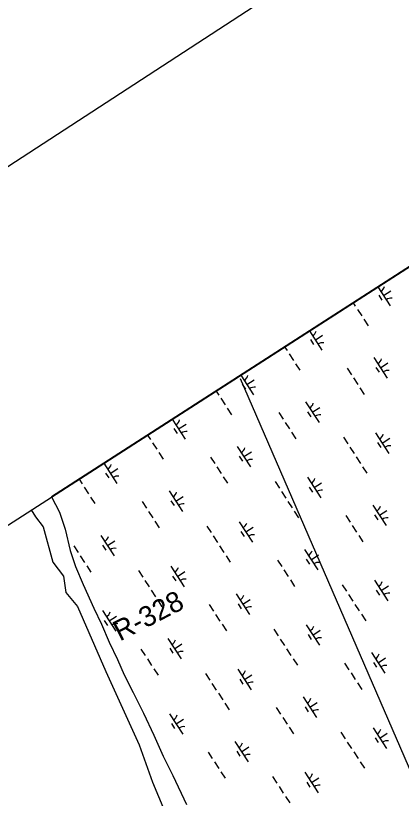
# Model space of a CAD drawing. Extents: x 3953924 to 3974542, y 193747 to 216192.
# Drawn here: x 3960506 to 3961293, y 210540 to 212138 of the extents above; entities that cross this region are included whole.
import ezdxf

# ---------------------------------------------------------------- set-up
doc = ezdxf.new("R2010")
doc.units = 0
for name, color, linetype in [('V-ANNO-SYMB', 7, 'Continuous'), ('V-GRID-FRAM', 7, 'Continuous'), ('V-RIVR-EDGE', 7, 'Continuous'), ('V-RIVR-RANG-IDEN', 7, 'Continuous'), ('V-UTIL-LINE', 7, 'Continuous'), ('V-WETL-SWMP', 7, 'Continuous')]:
    doc.layers.add(name, color=color, linetype=linetype)

msp = doc.modelspace()

# ---------------------------------------------------------------- linework, layer by layer
at = {"layer": 'V-ANNO-SYMB'}
msp.add_lwpolyline([(3955180.9, 208373.9), (3964205.1, 194510.7), (3973808.1, 200761.7), (3964783.9, 214624.9), (3955180.9, 208373.9)], dxfattribs=at)
at = {"layer": 'V-GRID-FRAM'}
msp.add_lwpolyline([(3964669.3, 213787.9), (3972946, 201072.9), (3966057, 196668.5), (3957950.8, 209463.9), (3964669.3, 213787.9)], dxfattribs=at)
at = {"layer": 'V-RIVR-EDGE'}
msp.add_lwpolyline([(3960538.1, 211129.1), (3960546.7, 211115.1), (3960562.1, 211094.9), (3960582.3, 211022.5), (3960603.7, 210994), (3960608.4, 210960.7), (3960632.2, 210932.2), (3960690.3, 210799.3), (3960758, 210649.7), (3960785.3, 210573.7), (3960818.5, 210494.2)], dxfattribs=at)
at = {"layer": 'V-UTIL-LINE'}
msp.add_lwpolyline([(3960964.1, 211397.1), (3962099.7, 208779.5)], dxfattribs=at)
at = {"layer": 'V-WETL-SWMP'}
for p, q in [((3962105.5, 212137.9), (3960579.5, 211155.8)), ((3961245.4, 211584.4), (3961270.6, 211545.7)), ((3961247.3, 211567.4), (3961253.8, 211557.4)), ((3961257, 211566.6), (3961272.1, 211576.4)), ((3961195, 211551.9), (3961199.4, 211545.1)), ((3961203.7, 211538.4), (3961212.5, 211525)), ((3961216.8, 211518.3), (3961225.5, 211504.9)), ((3961105.6, 211494.3), (3961131.2, 211454.9)), ((3961117.6, 211475.9), (3961132.7, 211485.7)), ((3961107.9, 211476.7), (3961114.4, 211466.6)), ((3961055.1, 211461.8), (3961060, 211454.4)), ((3961064.3, 211447.7), (3961073.1, 211434.2)), ((3961237.4, 211440.2), (3961264.7, 211398.3)), ((3961077.4, 211427.5), (3961086.1, 211414.1)), ((3961251, 211419.2), (3961266.1, 211429.1)), ((3961182.6, 211418.5), (3961191.4, 211405.1)), ((3961241.3, 211420.1), (3961247.8, 211410)), ((3960965.7, 211404.3), (3960991.8, 211364.2)), ((3960978.2, 211385.1), (3960993.3, 211394.9)), ((3961195.7, 211398.4), (3961204.4, 211385)), ((3960968.5, 211385.9), (3960975, 211375.9)), ((3961208.8, 211378.3), (3961217.5, 211364.9)), ((3960915.2, 211371.8), (3960920.6, 211363.6)), ((3960924.9, 211356.9), (3960933.6, 211343.5)), ((3961098, 211349.5), (3961125.3, 211307.5)), ((3960938, 211336.8), (3960946.7, 211323.4)), ((3961043.2, 211327.8), (3961051.9, 211314.4)), ((3961101.9, 211329.3), (3961108.4, 211319.3)), ((3961111.6, 211328.5), (3961126.7, 211338.3)), ((3960825.8, 211314.3), (3960852.4, 211273.4)), ((3960829, 211295.2), (3960835.6, 211285.1)), ((3960838.8, 211294.4), (3960853.9, 211304.2)), ((3961056.3, 211307.7), (3961065, 211294.3)), ((3960775.3, 211281.8), (3960781.2, 211272.9)), ((3961069.4, 211287.5), (3961078.1, 211274.1)), ((3961240.9, 211286.5), (3961268.1, 211244.6)), ((3960785.5, 211266.2), (3960794.2, 211252.8)), ((3961175, 211277.6), (3961183.8, 211264.2)), ((3961244.8, 211266.4), (3961251.3, 211256.3)), ((3961254.5, 211265.5), (3961269.6, 211275.4)), ((3960798.6, 211246.1), (3960807.3, 211232.6)), ((3960958.6, 211258.7), (3960985.8, 211216.8)), ((3960972.2, 211237.8), (3960987.3, 211247.6)), ((3961188.1, 211257.4), (3961196.9, 211244)), ((3960903.8, 211237), (3960912.5, 211223.6)), ((3960962.5, 211238.6), (3960969, 211228.5)), ((3961201.2, 211237.3), (3961210, 211223.9)), ((3960685.9, 211224.3), (3960713, 211182.7)), ((3960916.9, 211216.9), (3960925.6, 211203.5)), ((3961214.3, 211217.2), (3961223.1, 211203.8)), ((3960689.6, 211204.4), (3960696.2, 211194.4)), ((3960699.4, 211203.6), (3960714.5, 211213.4)), ((3960635.5, 211191.8), (3960641.7, 211182.1)), ((3960930, 211196.8), (3960938.7, 211183.4)), ((3961035.6, 211186.8), (3961044.4, 211173.4)), ((3961101.5, 211195.7), (3961128.7, 211153.8)), ((3961115.1, 211174.8), (3961130.2, 211184.6)), ((3960646.1, 211175.4), (3960654.8, 211162)), ((3960819.2, 211168), (3960846.4, 211126.1)), ((3961048.7, 211166.7), (3961057.5, 211153.3)), ((3961105.4, 211175.6), (3961111.9, 211165.6)), ((3960579.5, 211155.8), (3960595.7, 211124.3)), ((3960659.2, 211155.3), (3960667.9, 211141.9)), ((3960832.8, 211147), (3960847.9, 211156.8)), ((3960764.4, 211146.3), (3960773.1, 211132.9)), ((3960823.1, 211147.8), (3960829.6, 211137.8)), ((3961061.8, 211146.6), (3961070.6, 211133.2)), ((3961234.9, 211139.1), (3961262.2, 211097.2)), ((3960595.7, 211124.3), (3960607.4, 211089.6)), ((3960777.5, 211126.2), (3960786.2, 211112.8)), ((3961074.9, 211126.5), (3961083.6, 211113.1)), ((3961238.8, 211119), (3961245.3, 211108.9)), ((3961248.5, 211118.2), (3961263.6, 211128)), ((3960790.6, 211106.1), (3960799.3, 211092.6)), ((3960962.1, 211105), (3960989.3, 211063.1)), ((3961180.1, 211117.5), (3961188.9, 211104)), ((3960607.4, 211089.6), (3960617.2, 211046.5)), ((3960896.2, 211096.1), (3960905, 211082.7)), ((3960975.7, 211084.1), (3960990.8, 211093.9)), ((3961193.2, 211097.3), (3961201.9, 211083.9)), ((3960679.8, 211077.2), (3960707, 211035.3)), ((3960909.3, 211076), (3960918.1, 211062.5)), ((3960966, 211084.9), (3960972.5, 211074.8)), ((3961206.3, 211077.2), (3961215, 211063.8)), ((3960625, 211055.5), (3960633.7, 211042.1)), ((3960683.7, 211057.1), (3960690.2, 211047)), ((3960693.4, 211056.3), (3960708.5, 211066.1)), ((3960922.4, 211055.8), (3960931.2, 211042.4)), ((3960617.2, 211046.5), (3960628.6, 211013.3)), ((3961095.5, 211048.4), (3961122.8, 211006.5)), ((3960638.1, 211035.4), (3960646.8, 211022)), ((3960935.5, 211035.7), (3960944.2, 211022.3)), ((3961040.7, 211026.7), (3961049.4, 211013.3)), ((3961099.4, 211028.3), (3961105.9, 211018.2)), ((3961109.1, 211027.4), (3961124.2, 211037.3)), ((3960628.6, 211013.3), (3960643.9, 210977.2)), ((3960651.2, 211015.3), (3960659.9, 211001.9)), ((3960822.7, 211014.3), (3960849.9, 210972.4)), ((3961053.8, 211006.6), (3961062.5, 210993.2)), ((3960756.8, 211005.3), (3960765.6, 210991.9)), ((3960826.6, 210994.1), (3960833.1, 210984.1)), ((3960836.3, 210993.3), (3960851.4, 211003.1)), ((3960643.9, 210977.2), (3960665.7, 210928.6)), ((3960769.9, 210985.2), (3960778.7, 210971.8)), ((3961066.9, 210986.5), (3961075.6, 210973.1)), ((3961172.5, 210976.5), (3961181.3, 210963.1)), ((3961238.4, 210985.4), (3961265.6, 210943.5)), ((3961252, 210964.5), (3961267.1, 210974.3)), ((3960783, 210965.1), (3960791.7, 210951.7)), ((3961242.3, 210965.3), (3961248.8, 210955.2)), ((3960796.1, 210945), (3960804.8, 210931.6)), ((3960956.1, 210957.6), (3960983.3, 210915.7)), ((3960969.7, 210936.7), (3960984.8, 210946.5)), ((3961185.6, 210956.4), (3961194.4, 210943)), ((3960665.7, 210928.6), (3960681.1, 210895.7)), ((3960901.3, 210936), (3960910, 210922.6)), ((3960960, 210937.5), (3960966.5, 210927.5)), ((3961198.7, 210936.3), (3961207.5, 210922.9)), ((3960683.2, 210923.5), (3960710.5, 210881.6)), ((3960696.9, 210902.6), (3960712, 210912.4)), ((3960914.4, 210915.9), (3960923.1, 210902.4)), ((3961211.8, 210916.2), (3961220.6, 210902.7)), ((3960681.1, 210895.7), (3960697, 210859.1)), ((3960687.1, 210903.4), (3960693.7, 210893.3)), ((3960927.5, 210895.7), (3960936.2, 210882.3)), ((3961099, 210894.7), (3961126.2, 210852.8)), ((3961033.1, 210885.8), (3961041.9, 210872.3)), ((3961112.6, 210873.7), (3961127.7, 210883.6)), ((3960816.7, 210866.9), (3960843.9, 210825)), ((3961046.2, 210865.6), (3961055, 210852.2)), ((3961102.9, 210874.6), (3961109.4, 210864.5)), ((3960697, 210859.1), (3960713.9, 210824.1)), ((3960820.6, 210846.8), (3960827.1, 210836.7)), ((3960830.3, 210845.9), (3960845.4, 210855.8)), ((3960761.9, 210845.2), (3960770.6, 210831.8)), ((3961059.3, 210845.5), (3961068.1, 210832.1)), ((3961232.4, 210838.1), (3961259.7, 210796.2)), ((3960713.9, 210824.1), (3960727.4, 210792.6)), ((3960775, 210825.1), (3960783.7, 210811.7)), ((3961072.4, 210825.4), (3961081.2, 210812)), ((3961177.6, 210816.4), (3961186.4, 210803)), ((3961236.3, 210817.9), (3961242.8, 210807.9)), ((3961246, 210817.1), (3961261.1, 210826.9)), ((3960788.1, 210805), (3960796.8, 210791.6)), ((3960959.6, 210803.9), (3960986.8, 210762)), ((3960727.4, 210792.6), (3960746.1, 210756.2)), ((3960893.7, 210795), (3960902.5, 210781.6)), ((3960963.5, 210783.8), (3960970, 210773.8)), ((3960973.2, 210783), (3960988.3, 210792.8)), ((3961190.7, 210796.3), (3961199.4, 210782.9)), ((3960906.8, 210774.9), (3960915.6, 210761.5)), ((3961203.8, 210776.2), (3961212.5, 210762.8)), ((3960746.1, 210756.2), (3960766.9, 210714.4)), ((3960919.9, 210754.8), (3960928.7, 210741.4)), ((3960933, 210734.7), (3960941.7, 210721.3)), ((3961093, 210747.3), (3961120.3, 210705.4)), ((3961106.6, 210726.4), (3961121.7, 210736.2)), ((3961038.2, 210725.6), (3961047, 210712.2)), ((3961096.9, 210727.2), (3961103.4, 210717.1)), ((3960766.9, 210714.4), (3960788.1, 210669.3)), ((3960820.2, 210713.2), (3960847.4, 210671.3)), ((3961051.3, 210705.5), (3961060, 210692.1)), ((3960824.1, 210693.1), (3960830.6, 210683)), ((3960833.8, 210692.2), (3960848.9, 210702.1)), ((3961064.4, 210685.4), (3961073.1, 210672)), ((3961170, 210675.4), (3961178.8, 210662)), ((3961235.9, 210684.4), (3961263.1, 210642.5)), ((3961249.5, 210663.4), (3961264.6, 210673.2)), ((3960788.1, 210669.3), (3960807.1, 210626.6)), ((3960953.6, 210656.6), (3960980.9, 210614.7)), ((3961183.1, 210655.3), (3961191.9, 210641.9)), ((3961239.8, 210664.2), (3961246.3, 210654.2)), ((3960967.2, 210635.6), (3960982.3, 210645.4)), ((3960807.1, 210626.6), (3960827, 210586.8)), ((3960898.8, 210634.9), (3960907.5, 210621.5)), ((3960957.5, 210636.4), (3960964, 210626.4)), ((3961196.2, 210635.2), (3961205, 210621.8)), ((3960911.9, 210614.8), (3960920.6, 210601.4)), ((3961209.3, 210615.1), (3961218.1, 210601.7)), ((3960925, 210594.7), (3960933.7, 210581.3)), ((3961096.5, 210593.6), (3961123.7, 210551.7)), ((3960827, 210586.8), (3960854.7, 210528)), ((3961030.6, 210584.7), (3961039.4, 210571.3)), ((3961110.1, 210572.7), (3961125.2, 210582.5)), ((3961043.7, 210564.6), (3961052.5, 210551.2)), ((3961100.4, 210573.5), (3961106.9, 210563.4)), ((3960842.3, 210554.3), (3960842.9, 210554.7)), ((3961056.8, 210544.5), (3961065.6, 210531.1))]:
    msp.add_line(p, q, dxfattribs=at)
for centre, start, end in [((3961242.1, 211589.9), 302.2901, 343.8338), ((3961272.3, 211543.6), 82.2901, 123.8337), ((3961102.7, 211499.1), 302.2901, 343.8338), ((3961132.9, 211452.8), 82.2901, 123.8337), ((3961236.1, 211442.5), 302.2901, 343.8338), ((3961266.3, 211396.2), 82.2901, 123.8337), ((3960963.3, 211408.4), 302.2901, 343.8338), ((3960993.5, 211362.1), 82.2901, 123.8337), ((3961096.7, 211351.8), 302.2901, 343.8338), ((3960823.9, 211317.7), 302.2901, 343.8338), ((3961126.9, 211305.5), 82.2901, 123.8337), ((3960854.1, 211271.4), 82.2901, 123.8337), ((3961239.6, 211288.8), 302.2901, 343.8338), ((3960957.3, 211261), 302.2901, 343.8338), ((3961269.8, 211242.5), 82.2901, 123.8337), ((3960987.5, 211214.7), 82.2901, 123.8337), ((3960684.5, 211226.9), 302.2901, 343.8338), ((3960714.7, 211180.6), 82.2901, 123.8337), ((3961100.2, 211198.1), 302.2901, 343.8338), ((3961130.4, 211151.8), 82.2901, 123.8337), ((3960817.9, 211170.3), 302.2901, 343.8338), ((3960848.1, 211124), 82.2901, 123.8337), ((3961233.6, 211141.5), 302.2901, 343.8338), ((3960960.8, 211107.3), 302.2901, 343.8338), ((3961263.8, 211095.2), 82.2901, 123.8337), ((3960678.5, 211079.5), 302.2901, 343.8338), ((3960991, 211061), 82.2901, 123.8337), ((3960708.7, 211033.2), 82.2901, 123.8337), ((3961094.2, 211050.7), 302.2901, 343.8338), ((3960821.4, 211016.6), 302.2901, 343.8338), ((3961124.4, 211004.4), 82.2901, 123.8337), ((3960851.6, 210970.3), 82.2901, 123.8337), ((3961237.1, 210987.8), 302.2901, 343.8338), ((3961267.3, 210941.5), 82.2901, 123.8337), ((3960954.8, 210960), 302.2901, 343.8338), ((3960985, 210913.7), 82.2901, 123.8337), ((3960682, 210925.8), 302.2901, 343.8338), ((3960712.2, 210879.5), 82.2901, 123.8337), ((3961097.7, 210897), 302.2901, 343.8338), ((3960815.4, 210869.2), 302.2901, 343.8338), ((3961127.9, 210850.7), 82.2901, 123.8337), ((3960845.6, 210822.9), 82.2901, 123.8337), ((3961231.2, 210840.4), 302.2901, 343.8338), ((3960958.3, 210806.3), 302.2901, 343.8338), ((3961261.3, 210794.1), 82.2901, 123.8337), ((3960988.5, 210760), 82.2901, 123.8337), ((3961091.7, 210749.7), 302.2901, 343.8338), ((3961121.9, 210703.4), 82.2901, 123.8337), ((3960818.9, 210715.5), 302.2901, 343.8338), ((3960849.1, 210669.2), 82.2901, 123.8337), ((3961234.6, 210686.7), 302.2901, 343.8338), ((3961264.8, 210640.4), 82.2901, 123.8337), ((3960952.3, 210658.9), 302.2901, 343.8338), ((3960982.5, 210612.6), 82.2901, 123.8337), ((3961095.2, 210595.9), 302.2901, 343.8338), ((3961125.4, 210549.6), 82.2901, 123.8337)]:
    msp.add_arc(centre, 17.6, start, end, dxfattribs=at)

# ---------------------------------------------------------------- texts
at = {"layer": 'V-RIVR-RANG-IDEN'}
msp.add_text('R-328  ', height=41.5, rotation=27.1694, dxfattribs=at).set_placement((3960718.9, 210860.4))

doc.saveas('drawing.dxf')
